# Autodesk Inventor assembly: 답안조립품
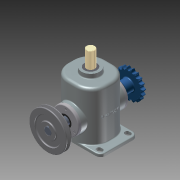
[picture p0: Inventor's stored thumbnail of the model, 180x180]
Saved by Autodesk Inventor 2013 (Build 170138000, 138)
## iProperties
Created: 2014-12
Part Number: 답안조립품
Document SubType Name: Assembly
Designer: cad10
Mass: 8322.52 g
Surface Area: 4222.88 cm^2
Volume: 1869.1 cm^3
Density: 4.4527 g/cm^3
Author: cad10
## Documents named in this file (15)
- C:\Documents and Settings\cad10\바탕 화면\341209V1028\답안조립품.iam
- C:\Documents and Settings\cad10\바탕 화면\341209V1028\본체.ipt
- C:\Documents and Settings\cad10\바탕 화면\341209V1028\M4x0.5.ipt
- C:\Documents and Settings\cad10\바탕 화면\341209V1028\베어링 6205.ipt
- C:\Documents and Settings\cad10\바탕 화면\341209V1028\체인 스프로킷.ipt
- C:\Documents and Settings\cad10\바탕 화면\341209V1028\커버.ipt
- C:\Documents and Settings\cad10\바탕 화면\341209V1028\멈춤나사 M5x0.5.ipt
- C:\Documents and Settings\cad10\바탕 화면\341209V1028\멈춤링.ipt
- C:\Documents and Settings\cad10\바탕 화면\341209V1028\V-벨트풀리.ipt
- C:\Documents and Settings\cad10\바탕 화면\341209V1028\오일실.ipt
- C:\Documents and Settings\cad10\바탕 화면\341209V1028\키 8x8.ipt
- C:\Documents and Settings\cad10\바탕 화면\341209V1028\편심축.ipt
- C:\Documents and Settings\cad10\바탕 화면\341209V1028\부시.ipt
- C:\Documents and Settings\cad10\바탕 화면\341209V1028\슬라이드.ipt
- C:\Documents and Settings\cad10\바탕 화면\341209V1028\7-가변스프링.ipt
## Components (9 placed, 4 different names)
1. 5-체인 스프로킷:1 — 각도:3
2. V-벨트풀리:1 — 각도:2
3. 7-가변스프링:1
4. M4x0.5:1
5. M4x0.5:2
6. M4x0.5:3
7. M4x0.5:4
8. M4x0.5:5
9. M4x0.5:6
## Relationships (2: Angle 2)
- 각도:2 [Angle]: V-벨트풀리:1
- 각도:3 [Angle]: 5-체인 스프로킷:1
